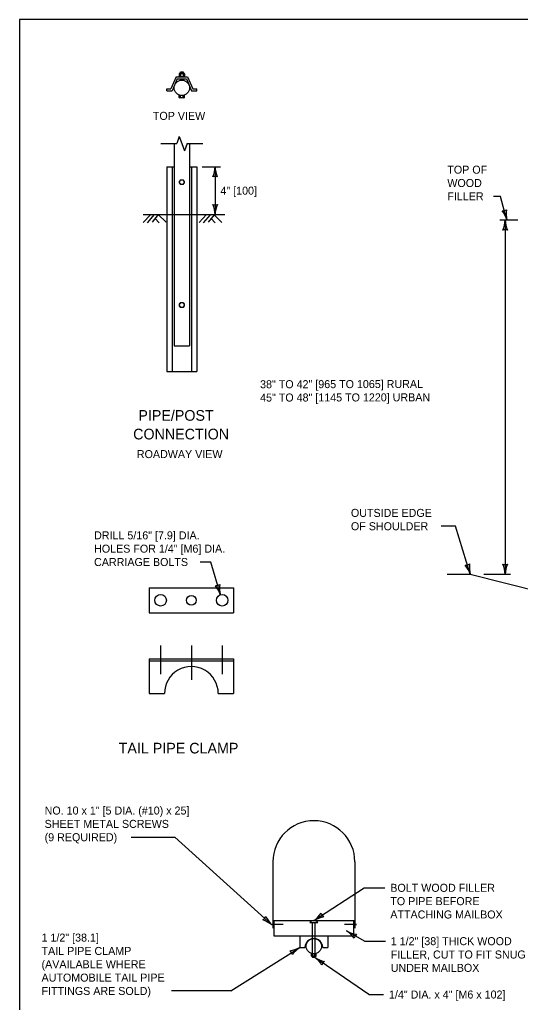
# Model space of a CAD drawing. Extents: x 49991.4 to 50021, y 49987.6 to 50011.4.
# Drawn here: x 50000.34 to 50004.09, y 50003.9 to 50011.26 of the extents above; entities that cross this region are included whole.
import ezdxf

# ---------------------------------------------------------------- set-up
doc = ezdxf.new("R2010")
doc.units = 0
for name, color, linetype in [('Level 1', 7, 'Continuous'), ('Level 2', 7, 'Continuous'), ('Level 3', 7, 'Continuous'), ('Level 4', 7, 'Continuous'), ('Level 5', 7, 'Continuous'), ('Level 6', 7, 'Continuous')]:
    doc.layers.add(name, color=color, linetype=linetype)

msp = doc.modelspace()

# ---------------------------------------------------------------- linework, layer by layer
at = {"layer": 'Level 1'}
for p, q in [((50001.5306, 50010.857), (50001.5335, 50010.8587)), ((50001.5306, 50010.8571), (50001.5306, 50010.8378)), ((50001.5335, 50010.8587), (50001.5693, 50010.8587)), ((50001.5394, 50010.8677), (50001.5424, 50010.8707)), ((50001.5394, 50010.8677), (50001.5394, 50010.8587)), ((50001.5394, 50010.8647), (50001.5634, 50010.8647)), ((50001.5408, 50010.8571), (50001.5408, 50010.8378)), ((50001.5424, 50010.8707), (50001.5604, 50010.8707)), ((50001.5424, 50010.8677), (50001.5604, 50010.8677)), ((50001.5424, 50010.8617), (50001.5604, 50010.8617)), ((50001.5634, 50010.8677), (50001.5604, 50010.8707)), ((50001.5619, 50010.8571), (50001.5619, 50010.8378)), ((50001.5634, 50010.8677), (50001.5634, 50010.8587)), ((50001.5722, 50010.8571), (50001.5693, 50010.8587)), ((50001.5722, 50010.857), (50001.5722, 50010.8378)), ((50001.5079, 50010.8334), (50001.4698, 50010.7438)), ((50001.5174, 50010.819), (50001.4793, 50010.7294)), ((50001.5079, 50010.8334), (50001.5948, 50010.8334)), ((50001.5174, 50010.819), (50001.5853, 50010.819)), ((50001.5274, 50010.8374), (50001.5306, 50010.8374)), ((50001.5274, 50010.8334), (50001.5274, 50010.8374)), ((50001.5274, 50010.8334), (50001.5514, 50010.8334)), ((50001.5306, 50010.8378), (50001.5722, 50010.8378)), ((50001.5306, 50010.8374), (50001.5722, 50010.8374)), ((50001.5335, 50010.8378), (50001.5335, 50010.8374)), ((50001.5394, 50010.819), (50001.5394, 50010.808)), ((50001.5514, 50010.8374), (50001.5514, 50010.8374)), ((50001.5514, 50010.8334), (50001.5514, 50010.8334)), ((50001.5514, 50010.8334), (50001.5754, 50010.8334)), ((50001.5634, 50010.819), (50001.5634, 50010.8079)), ((50001.5693, 50010.8378), (50001.5693, 50010.8374)), ((50001.5722, 50010.8374), (50001.5754, 50010.8374)), ((50001.5754, 50010.8334), (50001.5754, 50010.8374)), ((50001.5853, 50010.819), (50001.6234, 50010.7294)), ((50001.5948, 50010.8334), (50001.6329, 50010.7438)), ((50001.4386, 50010.7294), (50001.4386, 50010.7438)), ((50001.4386, 50010.7438), (50001.4698, 50010.7438)), ((50001.4386, 50010.7294), (50001.4793, 50010.7294)), ((50001.6234, 50010.7294), (50001.6642, 50010.7294)), ((50001.6329, 50010.7438), (50001.6642, 50010.7438)), ((50001.6642, 50010.7294), (50001.6642, 50010.7438)), ((50001.5306, 50010.6789), (50001.5306, 50010.694)), ((50001.5514, 50010.694), (50001.5306, 50010.694)), ((50001.5306, 50010.6788), (50001.5335, 50010.6772)), ((50001.5693, 50010.6772), (50001.5335, 50010.6772)), ((50001.5394, 50010.694), (50001.5394, 50010.6957)), ((50001.5408, 50010.6788), (50001.5408, 50010.694)), ((50001.5514, 50010.694), (50001.5514, 50010.694)), ((50001.5722, 50010.694), (50001.5514, 50010.694)), ((50001.5619, 50010.6788), (50001.5619, 50010.694)), ((50001.5634, 50010.694), (50001.5634, 50010.6957)), ((50001.5722, 50010.6789), (50001.5693, 50010.6772)), ((50001.5722, 50010.6788), (50001.5722, 50010.694)), ((50001.4938, 50010.3332), (50001.4938, 50009.8011)), ((50001.609, 50010.3332), (50001.609, 50009.8011)), ((50001.4386, 50010.1604), (50001.4938, 50010.1604)), ((50001.4386, 50010.1604), (50001.4386, 50009.8011)), ((50001.4794, 50010.1604), (50001.4794, 50009.8011)), ((50001.609, 50010.1604), (50001.6642, 50010.1604)), ((50001.6234, 50010.1604), (50001.6234, 50009.8011)), ((50001.6642, 50010.1604), (50001.6642, 50009.8011)), ((50001.541, 50010.0632), (50001.5306, 50010.0452)), ((50001.5306, 50010.0452), (50001.5409, 50010.0272)), ((50001.541, 50010.0632), (50001.5617, 50010.0632)), ((50001.5722, 50010.0452), (50001.5617, 50010.0632)), ((50001.5617, 50010.0272), (50001.5722, 50010.0452)), ((50001.5617, 50010.0272), (50001.5409, 50010.0272)), ((50001.3172, 50009.8008), (50001.261, 50009.7427)), ((50001.2617, 50009.8011), (50001.8738, 50009.8011)), ((50001.3441, 50009.8009), (50001.2925, 50009.7398)), ((50001.3739, 50009.801), (50001.329, 50009.7437)), ((50001.3814, 50009.7406), (50001.3515, 50009.7723)), ((50001.3739, 50009.801), (50001.4328, 50009.7439)), ((50001.7367, 50009.8009), (50001.6802, 50009.743)), ((50001.7636, 50009.8008), (50001.7115, 50009.7399)), ((50001.7934, 50009.8008), (50001.7482, 50009.7437)), ((50001.8004, 50009.7403), (50001.7709, 50009.7723)), ((50001.7934, 50009.8008), (50001.852, 50009.7433)), ((50001.541, 50009.1416), (50001.5306, 50009.1236)), ((50001.5306, 50009.1236), (50001.5409, 50009.1056)), ((50001.5617, 50009.1056), (50001.5409, 50009.1056)), ((50001.541, 50009.1416), (50001.5617, 50009.1416)), ((50001.5722, 50009.1236), (50001.5617, 50009.1416)), ((50001.5617, 50009.1056), (50001.5722, 50009.1236)), ((50003.5408, 50007.1049), (50003.7136, 50007.1049)), ((50003.7136, 50007.1049), (50007.0128, 50006.2801)), ((50001.3059, 50007.0036), (50001.9395, 50007.0036)), ((50001.3059, 50007.0036), (50001.3059, 50006.8164)), ((50001.9395, 50007.0036), (50001.9395, 50006.8164)), ((50001.3059, 50006.8164), (50001.9395, 50006.8164)), ((50001.3059, 50006.4708), (50001.9395, 50006.4708)), ((50001.3059, 50006.4708), (50001.3059, 50006.2116)), ((50001.9395, 50006.4708), (50001.9395, 50006.2116)), ((50001.3059, 50006.2116), (50001.4211, 50006.2116)), ((50001.8243, 50006.2116), (50001.9395, 50006.2116)), ((50002.2337, 50004.9505), (50002.2337, 50004.4512)), ((50002.848, 50004.9505), (50002.848, 50004.4512)), ((50002.2265, 50004.4854), (50002.2265, 50004.4746)), ((50002.3105, 50004.48), (50002.2265, 50004.48)), ((50002.2337, 50004.5088), (50002.848, 50004.5088)), ((50002.2409, 50004.5088), (50002.2409, 50004.3936)), ((50002.51, 50004.4938), (50002.5717, 50004.4938)), ((50002.8552, 50004.48), (50002.7713, 50004.48)), ((50002.8408, 50004.3936), (50002.8408, 50004.5088)), ((50002.8552, 50004.4854), (50002.8552, 50004.4746)), ((50002.2409, 50004.3936), (50002.8408, 50004.3936)), ((50002.4353, 50004.3936), (50002.4353, 50004.3072)), ((50002.6464, 50004.3936), (50002.6464, 50004.3072)), ((50002.4353, 50004.3072), (50002.4736, 50004.3072)), ((50002.608, 50004.3072), (50002.6464, 50004.3072)), ((50002.5242, 50004.2435), (50002.5242, 50004.2589)), ((50002.5574, 50004.2589), (50002.5242, 50004.2589)), ((50002.5242, 50004.2435), (50002.5265, 50004.2422)), ((50002.5265, 50004.2589), (50002.5265, 50004.2593)), ((50002.5552, 50004.2593), (50002.5265, 50004.2593)), ((50002.5552, 50004.2422), (50002.5265, 50004.2422)), ((50002.5312, 50004.2593), (50002.5312, 50004.2606)), ((50002.5312, 50004.235), (50002.5312, 50004.2422)), ((50002.5505, 50004.2374), (50002.5312, 50004.2374)), ((50002.5312, 50004.235), (50002.5337, 50004.2326)), ((50002.5325, 50004.2434), (50002.5325, 50004.2589)), ((50002.5481, 50004.2398), (50002.5337, 50004.2398)), ((50002.5481, 50004.235), (50002.5337, 50004.235)), ((50002.5481, 50004.2326), (50002.5337, 50004.2326)), ((50002.5505, 50004.235), (50002.5481, 50004.2326)), ((50002.5492, 50004.2434), (50002.5492, 50004.2589)), ((50002.5505, 50004.2593), (50002.5505, 50004.2606)), ((50002.5505, 50004.235), (50002.5505, 50004.2422)), ((50002.5552, 50004.2589), (50002.5552, 50004.2593)), ((50002.5574, 50004.2435), (50002.5552, 50004.2422)), ((50002.5574, 50004.2435), (50002.5574, 50004.2589))]:
    msp.add_line(p, q, dxfattribs=at)
msp.add_lwpolyline([(50008.6146, 50011.2628), (50000.3356, 50011.2628), (50000.3356, 50000.0624), (50008.6146, 50000.0624)], close=True, dxfattribs=at)
for centre, radius in [((50001.5514, 50010.7516), 0.0576), ((50001.5514, 50010.0452), 0.018), ((50001.5514, 50009.1236), 0.018), ((50001.3922, 50006.91), 0.0432), ((50001.853, 50006.91), 0.0432), ((50001.6226, 50006.91), 0.036), ((50002.5408, 50004.3168), 0.0576)]:
    msp.add_circle(centre, radius, dxfattribs=at)
for centre, radius, start, end in [((50001.5358, 50010.8497), 0.009, 55.59477, 125.17175), ((50001.5514, 50010.8227), 0.036, 73.01489, 106.97814), ((50001.567, 50010.8497), 0.009, 54.6726, 124.40523), ((50001.5358, 50010.6862), 0.009, 234.6726, 304.40523), ((50001.5514, 50010.7132), 0.036, 253.01489, 286.97814), ((50001.567, 50010.6862), 0.009, 235.59477, 305.17175), ((50001.6226, 50006.2116), 0.2016, 359.99977, 179.99977), ((50002.5408, 50004.9504), 0.3072, 0, 180), ((50002.5408, 50004.4697), 0.0392, 38.04168, 141.95832), ((50002.5408, 50004.3073), 0.0672, 359.99231, 180.00769), ((50002.5284, 50004.2494), 0.0072, 234.6726, 304.40523), ((50002.5408, 50004.271), 0.0288, 253.01489, 286.97814), ((50002.5533, 50004.2494), 0.0072, 235.59477, 305.17175)]:
    msp.add_arc(centre, radius, start, end, dxfattribs=at)
at = {"layer": 'Level 3'}
for p, q in [((50001.7042, 50010.1604), (50001.8405, 50010.1604)), ((50001.8005, 50010.1604), (50001.8005, 50009.8011)), ((50003.9409, 50009.9382), (50003.8885, 50009.9382)), ((50003.9884, 50009.7605), (50003.9409, 50009.9382)), ((50004.0685, 50009.7605), (50003.9346, 50009.7605)), ((50003.9746, 50009.7605), (50003.9746, 50007.1049)), ((50003.6026, 50007.4652), (50003.496, 50007.4652)), ((50003.7136, 50007.1049), (50003.6026, 50007.4652)), ((50001.7682, 50007.197), (50001.6875, 50007.197)), ((50001.8408, 50006.9515), (50001.7682, 50007.197)), ((50003.8136, 50007.1049), (50004.0146, 50007.1049)), ((50002.5408, 50004.5088), (50002.9185, 50004.7547)), ((50002.9185, 50004.7547), (50003.0738, 50004.7547)), ((50002.9197, 50004.3547), (50002.7865, 50004.4313)), ((50001.9178, 50003.9815), (50002.4353, 50004.3072)), ((50002.9197, 50004.3547), (50003.0771, 50004.3547)), ((50002.9528, 50003.9547), (50002.5481, 50004.2326)), ((50001.9178, 50003.9815), (50001.4741, 50003.9815)), ((50002.9528, 50003.9547), (50003.0639, 50003.9547))]:
    msp.add_line(p, q, dxfattribs=at)
msp.add_lwpolyline([(50001.1714, 50005.1339), (50001.4982, 50005.1339), (50002.2265, 50004.4765)], dxfattribs=at)
for centre, radius, start, end in [((50001.5784, 50010.1696), 0.2223, 337.45601, 357.63952), ((50002.0332, 50010.1719), 0.233, 182.82731, 202.07716), ((50001.8005, 50010.0322), 0.0548, 72.13882, 107.86118), ((50001.8005, 50009.9293), 0.0548, 252.13882, 287.86118), ((50001.5678, 50009.7896), 0.233, 2.82731, 22.07716), ((50002.0226, 50009.7919), 0.2223, 157.45601, 177.63952), ((50003.9553, 50009.8844), 0.0548, 267.10435, 302.82671), ((50003.7665, 50009.6893), 0.233, 17.79284, 37.04269), ((50004.2054, 50009.809), 0.2223, 172.42154, 192.60505), ((50003.7525, 50009.7697), 0.2223, 337.45601, 357.63952), ((50004.2073, 50009.772), 0.233, 182.82731, 202.07716), ((50003.9746, 50009.6323), 0.0548, 72.13882, 107.86118), ((50003.6759, 50007.2274), 0.0548, 269.26166, 304.98402), ((50003.4946, 50007.0254), 0.233, 19.95015, 39.2), ((50003.9286, 50007.1616), 0.2223, 174.57885, 194.76236), ((50003.9746, 50007.2331), 0.0548, 252.13882, 287.86118), ((50003.7419, 50007.0934), 0.233, 2.82731, 22.07716), ((50004.1967, 50007.0957), 0.2223, 157.45601, 177.63952), ((50001.8045, 50007.0744), 0.0548, 268.59434, 304.3167), ((50002.0564, 50007.0056), 0.2223, 173.91153, 194.09504), ((50001.6209, 50006.8745), 0.233, 19.28283, 38.53268), ((50002.1307, 50004.5617), 0.0548, 300.46252, 336.18488), ((50002.381, 50004.6363), 0.2223, 205.77971, 225.96322), ((50002.4052, 50004.6983), 0.233, 305.58919, 324.83904), ((50002.6533, 50004.3171), 0.2223, 100.21789, 120.40139), ((50002.6487, 50004.5782), 0.0548, 194.90069, 230.62306), ((50002.0803, 50004.295), 0.233, 51.15101, 70.40086), ((50002.6644, 50004.2455), 0.2223, 36.49858, 56.68209), ((50002.8964, 50004.6368), 0.233, 241.86988, 261.11973), ((50002.8965, 50004.3653), 0.0548, 131.18139, 166.90375), ((50002.3306, 50004.5033), 0.2223, 277.91925, 298.10276), ((50002.5632, 50004.1124), 0.233, 123.29055, 142.5404), ((50002.3248, 50004.2422), 0.0548, 12.60206, 48.32442), ((50002.4151, 50004.0545), 0.2223, 33.06771, 53.25122), ((50002.6701, 50004.4311), 0.233, 238.43901, 257.68886), ((50002.6539, 50004.1602), 0.0548, 127.75052, 163.47288)]:
    msp.add_arc(centre, radius, start, end, dxfattribs=at)
at = {"layer": 'Level 4'}
for p, q in [((50001.4386, 50009.8011), (50001.4386, 50008.6245)), ((50001.4794, 50009.8011), (50001.4794, 50008.6245)), ((50001.4938, 50009.8011), (50001.4938, 50008.8164)), ((50001.609, 50009.8011), (50001.609, 50008.8164)), ((50001.6234, 50009.8011), (50001.6234, 50008.6245)), ((50001.6642, 50009.8011), (50001.6642, 50008.6245)), ((50001.4938, 50008.8164), (50001.609, 50008.8164)), ((50001.4386, 50008.6245), (50001.6642, 50008.6245)), ((50001.3059, 50006.4564), (50001.9395, 50006.4564)), ((50002.5312, 50004.2593), (50002.5312, 50004.4938)), ((50002.5505, 50004.2593), (50002.5505, 50004.4938))]:
    msp.add_line(p, q, dxfattribs=at)
at = {"layer": 'Level 5'}
for p, q in [((50001.3923, 50006.5708), (50001.3923, 50006.3564)), ((50001.6227, 50006.5708), (50001.6227, 50006.3132)), ((50001.8531, 50006.5708), (50001.8531, 50006.3564))]:
    msp.add_line(p, q, dxfattribs=at)
at = {"layer": 'Level 6'}
for p, q in [((50001.532, 50010.388), (50001.5125, 50010.3332)), ((50001.532, 50010.388), (50001.5514, 50010.3332)), ((50001.3938, 50010.3332), (50001.5125, 50010.3332)), ((50001.5514, 50010.3332), (50001.5708, 50010.2784)), ((50001.5903, 50010.3332), (50001.5708, 50010.2784)), ((50001.5903, 50010.3332), (50001.709, 50010.3332))]:
    msp.add_line(p, q, dxfattribs=at)

# ---------------------------------------------------------------- texts
at = {"layer": 'Level 2'}
for s, height, p in [('TOP VIEW', 0.06, (50001.3341, 50010.5116)), ('TOP OF', 0.06, (50003.5412, 50010.1082)), ('WOOD', 0.06, (50003.5412, 50010.0082)), ('4" [100]', 0.06, (50001.8405, 50009.9508)), ('FILLER', 0.06, (50003.5412, 50009.9082)), ('PIPE/POST', 0.08, (50001.2252, 50008.256)), ('CONNECTION', 0.08, (50001.1864, 50008.116)), ('ROADWAY VIEW', 0.06, (50001.2141, 50007.976)), ('OUTSIDE EDGE', 0.06, (50002.8187, 50007.5352)), ('OF SHOULDER', 0.06, (50002.8187, 50007.4352)), ('DRILL 5/16" [7.9] DIA.', 0.06, (50000.8934, 50007.367)), ('HOLES FOR 1/4" [M6] DIA. ', 0.06, (50000.8934, 50007.267)), ('CARRIAGE BOLTS', 0.06, (50000.8934, 50007.167)), ('TAIL PIPE CLAMP', 0.08, (50001.0778, 50005.7618)), ('NO. 10 x 1" [5 DIA. (#10) x 25]', 0.06, (50000.5228, 50005.3039)), ('SHEET METAL SCREWS', 0.06, (50000.5228, 50005.2039)), ('(9 REQUIRED)', 0.06, (50000.5228, 50005.1039)), ('BOLT WOOD FILLER', 0.06, (50003.1138, 50004.7247)), ('TO PIPE BEFORE', 0.06, (50003.1138, 50004.6247)), ('ATTACHING MAILBOX', 0.06, (50003.1138, 50004.5247)), ('1 1/2" [38.1]', 0.06, (50000.4996, 50004.3515)), ('1 1/2" [38] THICK WOOD', 0.06, (50003.1171, 50004.3247)), ('TAIL PIPE CLAMP', 0.06, (50000.4996, 50004.2515)), ('FILLER, CUT TO FIT SNUG', 0.06, (50003.1171, 50004.2247)), ('(AVAILABLE WHERE', 0.06, (50000.4996, 50004.1515)), ('UNDER MAILBOX', 0.06, (50003.1171, 50004.1247)), ('AUTOMOBILE TAIL PIPE', 0.06, (50000.4996, 50004.0515)), ('FITTINGS ARE SOLD)', 0.06, (50000.4996, 50003.9515)), ('1/4" DIA. x 4" [M6 x 102]', 0.06, (50003.1039, 50003.9247))]:
    msp.add_text(s, height=height, dxfattribs=at).set_placement(p)
for s, p in [('38" TO 42" [965 TO 1065] RURAL', (50002.1378, 50008.4996)), ('45" TO 48" [1145 TO 1220] URBAN', (50002.138, 50008.3996))]:
    msp.add_text(s, height=0.06, rotation=0.1, dxfattribs=at).set_placement(p)

doc.saveas('drawing.dxf')
